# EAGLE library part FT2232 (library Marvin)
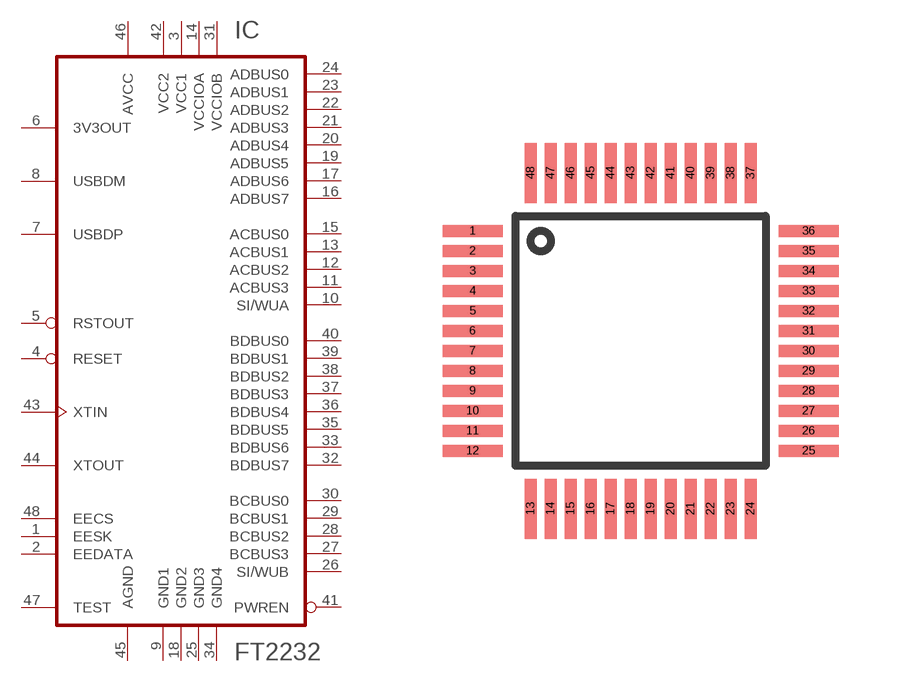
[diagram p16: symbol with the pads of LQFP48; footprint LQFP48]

Designator prefix IC

## FT2232  [LQFP48]
1  EESK
2  EEDATA
3  VCC1
4  RESET
5  RSTOUT
6  3V3OUT
7  USBDP
8  USBDM
9  GND1
10  SI/WUA
11  ACBUS3
12  ACBUS2
13  ACBUS1
14  VCCIOA
15  ACBUS0
16  ADBUS7
17  ADBUS6
18  GND2
19  ADBUS5
20  ADBUS4
21  ADBUS3
22  ADBUS2
23  ADBUS1
24  ADBUS0
25  GND3
26  SI/WUB
27  BCBUS3
28  BCBUS2
29  BCBUS1
30  BCBUS0
31  VCCIOB
32  BDBUS7
33  BDBUS6
34  GND4
35  BDBUS5
36  BDBUS4
37  BDBUS3
38  BDBUS2
39  BDBUS1
40  BDBUS0
41  PWREN
42  VCC2
43  XTIN
44  XTOUT
45  AGND
46  AVCC
47  TEST
48  EECS

## Footprint LQFP48 (pad centres in mm)
smd 1.5 x 0.3: 1 -4.2,2.75; 2 -4.2,2.25; 3 -4.2,1.75; 4 -4.2,1.25; 5 -4.2,0.75; 6 -4.2,0.25; 7 -4.2,-0.25; 8 -4.2,-0.75; 9 -4.2,-1.25; 10 -4.2,-1.75; 11 -4.2,-2.25; 12 -4.2,-2.75; 25 4.2,-2.75; 26 4.2,-2.25; 27 4.2,-1.75; 28 4.2,-1.25; 29 4.2,-0.75; 30 4.2,-0.25; 31 4.2,0.25; 32 4.2,0.75; 33 4.2,1.25; 34 4.2,1.75; 35 4.2,2.25; 36 4.2,2.75
smd 0.3 x 1.5: 13 -2.75,-4.2; 14 -2.25,-4.2; 15 -1.75,-4.2; 16 -1.25,-4.2; 17 -0.75,-4.2; 18 -0.25,-4.2; 19 0.25,-4.2; 20 0.75,-4.2; 21 1.25,-4.2; 22 1.75,-4.2; 23 2.25,-4.2; 24 2.75,-4.2; 37 2.75,4.2; 38 2.25,4.2; 39 1.75,4.2; 40 1.25,4.2; 41 0.75,4.2; 42 0.25,4.2; 43 -0.25,4.2; 44 -0.75,4.2; 45 -1.25,4.2; 46 -1.75,4.2; 47 -2.25,4.2; 48 -2.75,4.2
